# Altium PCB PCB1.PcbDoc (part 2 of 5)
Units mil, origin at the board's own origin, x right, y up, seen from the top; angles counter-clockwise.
Board outline 4463 x 4481 mil, 2 copper layers (Top Layer, Bottom Layer); 0 components, 111 nets, 310 pads, 0 vias.
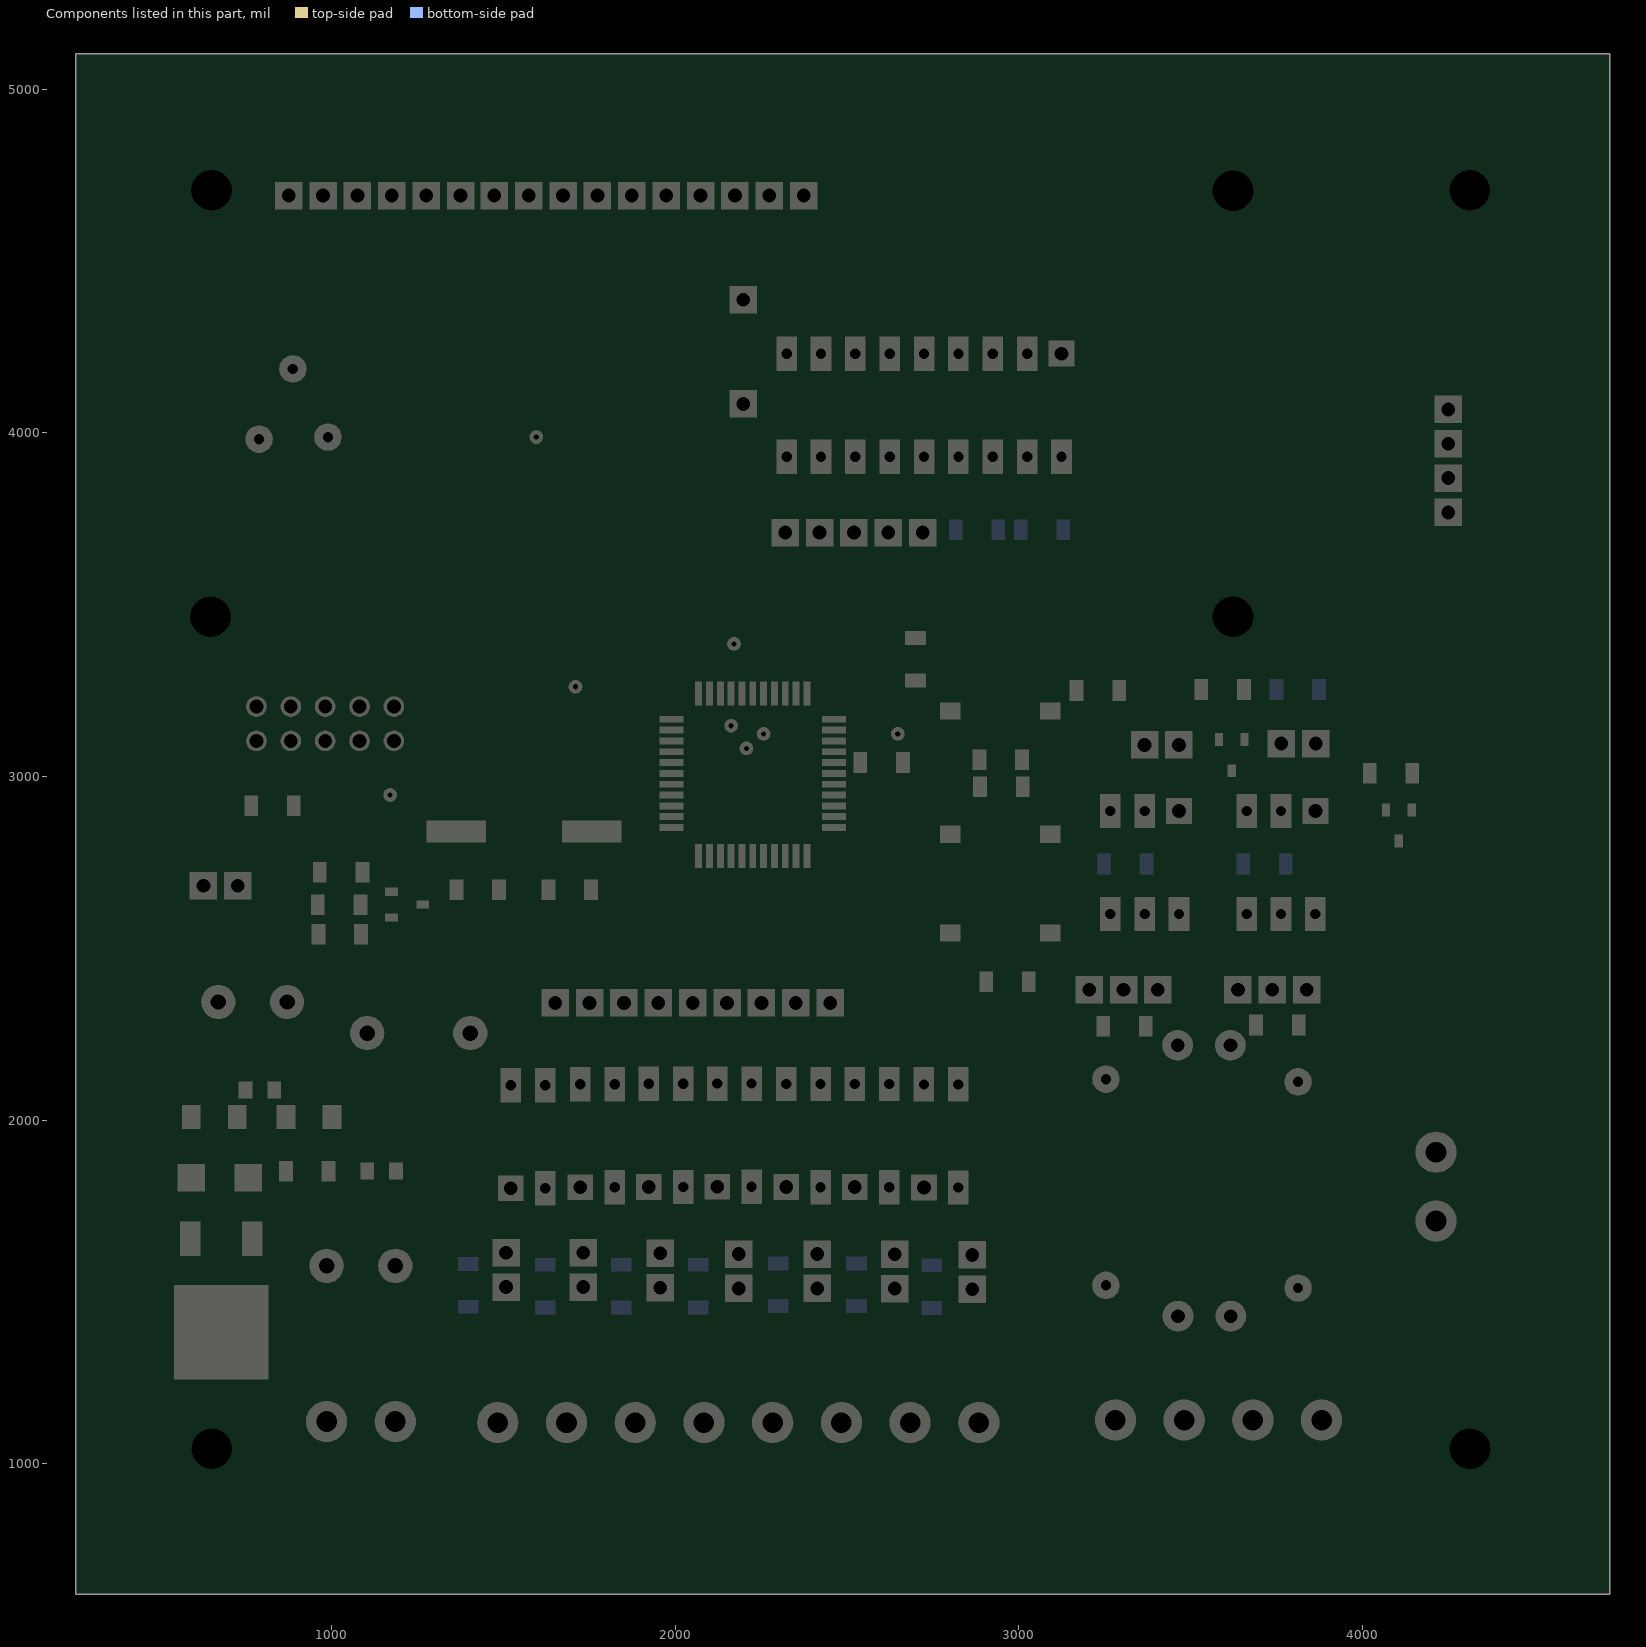
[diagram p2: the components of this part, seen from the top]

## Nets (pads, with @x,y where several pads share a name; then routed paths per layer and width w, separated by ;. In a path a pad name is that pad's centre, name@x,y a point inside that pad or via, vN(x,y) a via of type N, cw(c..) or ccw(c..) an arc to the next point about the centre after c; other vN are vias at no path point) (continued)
copper on no net: (continued)
  Top Layer w15: 514.04,931.9 4450.24,931.9 ; 514.04,956.9 4450.24,956.9 ; 514.04,981.9 591.54,981.9 ; 514.04,1006.9 566.54,1006.9 ; 514.04,1031.9 565.74,1031.9 ; 514.04,1056.9 565.74,1056.9 ; 514.04,1081.9 568.24,1081.9 ; 514.04,1106.9 593.24,1106.9 ; 514.04,1131.9 898.64,1131.9 ; 514.04,1156.9 898.64,1156.9 ; 514.04,1181.9 921.24,1181.9 ; 514.04,1206.9 946.24,1206.9 ; 514.04,1231.9 514.64,1231.9 ; 514.04,1256.9 514.64,1256.9 ; 514.04,1281.9 514.64,1281.9 ; 514.04,1306.9 514.64,1306.9 ; 514.04,1331.9 514.64,1331.9 ; 514.04,1356.9 514.64,1356.9 ; 514.04,1381.9 514.64,1381.9 ; 514.04,1406.9 514.64,1406.9 ; 514.04,1431.9 514.64,1431.9 ; 514.04,1456.9 514.64,1456.9 ; 514.04,1481.9 514.64,1481.9 ; 514.04,1506.9 514.64,1506.9 ; 514.04,1531.9 514.64,1531.9 ; 514.04,1556.9 908.64,1556.9 ; 514.04,1581.9 532.14,1581.9 ; 514.04,1606.9 532.14,1606.9 ; 514.04,1631.9 532.14,1631.9 ; 514.04,1656.9 532.14,1656.9 ; 514.04,1681.9 532.14,1681.9 ; 514.04,1706.9 532.14,1706.9 ; 514.04,1731.9 532.14,1731.9 ; 514.04,1756.9 547.14,1756.9 ; 514.04,1781.9 524.94,1781.9 ; 514.04,1806.9 524.94,1806.9 ; 514.04,1831.9 524.94,1831.9 ; 514.04,1856.9 524.94,1856.9 ; 514.04,1881.9 524.94,1881.9 ; 514.04,1906.9 549.94,1906.9 ; 514.04,1931.9 549.94,1931.9 ; 514.04,1956.9 537.44,1956.9 ; 514.04,1981.9 537.44,1981.9 ; 514.04,2006.9 537.44,2006.9 ; 514.04,2031.9 537.44,2031.9 ; 514.04,2056.9 537.44,2056.9 ; 514.04,2081.9 549.94,2081.9 ; 514.04,2106.9 571.34,2106.9 ; 514.04,2131.9 702.44,2131.9 ; 514.04,2156.9 709.94,2156.9 ; 514.04,2181.9 709.94,2181.9 ; 514.04,2206.9 709.94,2206.9 ; 514.04,2231.9 709.94,2231.9 ; 514.04,2256.9 709.94,2256.9 ; 514.04,2281.9 623.24,2281.9 ; 514.04,2306.9 598.24,2306.9 ; 514.04,2331.9 593.64,2331.9 ; 514.04,2356.9 593.64,2356.9 ; 514.04,2381.9 599.84,2381.9 ; 514.04,2406.9 624.84,2406.9 ; 514.04,2431.9 930.64,2431.9 ; 514.04,2456.9 930.64,2456.9 ; 514.04,2481.9 930.64,2481.9 ; 514.04,2506.9 911.04,2506.9 ; 514.04,2531.9 886.04,2531.9 ; 514.04,2556.9 872.34,2556.9 ; 514.04,2581.9 872.34,2581.9 ; 514.04,2606.9 872.34,2606.9 ; 514.04,2631.9 560.34,2631.9 ; 514.04,2656.9 560.34,2656.9 ; 514.04,2681.9 560.34,2681.9 ; 514.04,2706.9 560.34,2706.9 ; 514.04,2731.9 560.34,2731.9 ; 514.04,2756.9 692.84,2756.9 ; 514.04,2781.9 692.84,2781.9 ; 514.04,2806.9 692.84,2806.9 ; 514.04,2831.9 692.84,2831.9 ; 514.04,2856.9 707.84,2856.9 ; 514.04,2881.9 719.34,2881.9 ; 514.04,2906.9 719.34,2906.9 ; 514.04,2931.9 719.34,2931.9 ; 514.04,2956.9 719.34,2956.9 ; 514.04,2981.9 931.44,2981.9 ; 514.04,3006.9 674.04,3006.9 ; 514.04,3031.9 665.34,3031.9 ; 514.04,3056.9 665.34,3056.9 ; 514.04,3081.9 665.34,3081.9 ; 514.04,3106.9 665.34,3106.9 ; 514.04,3131.9 665.34,3131.9 ; 514.04,3156.9 665.34,3156.9 ; 514.04,3181.9 665.34,3181.9 ; 514.04,3206.9 665.34,3206.9 ; 514.04,3231.9 665.34,3231.9 ; 514.04,3256.9 675.34,3256.9 ; 514.04,3281.9 700.34,3281.9 ; 514.04,3306.9 725.34,3306.9 ; 514.04,3331.9 750.34,3331.9 ; 514.04,3356.9 754.64,3356.9 ; 514.04,3381.9 608.34,3381.9 ; 514.04,3406.9 583.34,3406.9 ; 514.04,3431.9 561.74,3431.9 ; 514.04,3456.9 561.74,3456.9 ; 514.04,3481.9 561.74,3481.9 ; 514.04,3506.9 568.44,3506.9 ; 514.04,3531.9 593.44,3531.9 ; 514.04,3556.9 754.64,3556.9 ; 514.04,3581.9 754.64,3581.9 ; 514.04,3606.9 754.64,3606.9 ; 514.04,3631.9 754.64,3631.9 ; 514.04,3656.9 754.64,3656.9 ; 514.04,3681.9 754.64,3681.9 ; 514.04,3706.9 754.64,3706.9 ; 514.04,3731.9 754.64,3731.9 ; 514.04,3756.9 754.64,3756.9 ; 514.04,3781.9 754.64,3781.9 ; 514.04,3806.9 754.64,3806.9 ; 514.04,3831.9 754.64,3831.9 ; 514.04,3856.9 754.64,3856.9 ; 514.04,3881.9 754.64,3881.9 ; 514.04,3906.9 754.64,3906.9 ; 514.04,3931.9 743.54,3931.9 ; 514.04,3956.9 722.14,3956.9 ; 514.04,3981.9 722.14,3981.9 ; 514.04,4006.9 722.14,4006.9 ; 514.04,4031.9 744.94,4031.9 ; 514.04,4056.9 1056.24,4056.9 ; 514.04,4081.9 1056.24,4081.9 ; 514.04,4106.9 1056.24,4106.9 ; 514.04,4131.9 846.34,4131.9 ; 514.04,4156.9 821.34,4156.9 ; 514.04,4181.9 820.64,4181.9 ; 514.04,4206.9 820.64,4206.9 ; 514.04,4231.9 839.04,4231.9 839.04,4433.2 ; 514.04,4256.9 1015.34,4256.9 ; 514.04,4281.9 990.34,4281.9 ; 514.04,4306.9 965.34,4306.9 ; 514.04,4331.9 940.34,4331.9 ; 514.04,4356.9 915.34,4356.9 ; 514.04,4381.9 890.34,4381.9 ; 514.04,4406.9 865.34,4406.9 ; 514.04,4431.9 840.34,4431.9 ; 514.04,4456.9 815.34,4456.9 ; 514.04,4481.9 790.34,4481.9 ; 514.04,4506.9 765.74,4506.9 ; 514.04,4531.9 765.74,4531.9 ; 514.04,4556.9 765.74,4556.9 ; 514.04,4581.9 765.74,4581.9 ; 514.04,4606.9 765.74,4606.9 ; 514.04,4631.9 602.84,4631.9 ; 514.04,4656.9 577.84,4656.9 ; 514.04,4681.9 564.94,4681.9 ; 514.04,4706.9 564.94,4706.9 ; 514.04,4731.9 564.94,4731.9 ; 514.04,4756.9 580.34,4756.9 ; 514.04,4781.9 605.34,4781.9 ; 514.04,4806.9 4450.24,4806.9 ; 514.04,4831.9 4450.24,4831.9 ; 539.04,906.9 539.04,1217.6 ; 539.04,1547.6 539.04,1577.1 ; 539.04,1732.1 539.04,1764.2 ; 539.04,1899.2 539.04,1946.4 ; 539.04,2071.4 539.04,4841.9 ; 564.04,906.9 564.04,1217.6 ; 564.04,1547.6 564.04,1577.1 ; 564.04,2099.7 564.04,2614.6 ; 564.04,2749.6 564.04,3426.2 ; 564.04,3502.5 564.04,4841.9 ; 589.04,906.9 589.04,984.4 ; 589.04,1102.7 589.04,1217.6 ; 589.04,1547.6 589.04,1577.1 ; 589.04,2124.7 589.04,2614.6 ; 589.04,2749.6 589.04,3401.2 ; 589.04,3527.5 589.04,4645.7 ; 589.04,4765.6 589.04,4841.9 ; 614.04,906.9 614.04,959.4 ; 614.04,1127.7 614.04,1217.6 ; 614.04,1547.6 614.04,1577.1 ; 614.04,2130.1 614.04,2291.1 ; 614.04,2396.1 614.04,2614.6 ; 614.04,2749.6 614.04,3377.8 ; 614.04,3550.9 614.04,4620.7 ; 614.04,4790.6 614.04,4841.9 ; 632.14,1756.9 715.24,1756.9 ; 634.94,1906.9 820.54,1906.9 ; 634.94,1931.9 825.54,1931.9 ; 639.04,906.9 639.04,957 ; 639.04,1130.1 639.04,1217.6 ; 639.04,1547.6 639.04,1577.1 ; 639.04,1732.1 639.04,1764.2 ; 639.04,1899.2 639.04,1946.4 ; 639.04,2130.1 639.04,2266.1 ; 639.04,2614.6 639.04,2421.1 ; 639.04,2749.6 639.04,3377.8 ; 639.04,3550.9 639.04,4619.1 ; 639.04,4792.2 639.04,4841.9 ; 647.14,1581.9 712.14,1581.9 ; 647.14,1606.9 712.14,1606.9 ; 647.14,1631.9 712.14,1631.9 ; 647.14,1656.9 712.14,1656.9 ; 647.14,1681.9 712.14,1681.9 ; 647.14,1706.9 712.14,1706.9 ; 647.14,1731.9 712.14,1731.9 ; 647.44,1956.9 671.24,1956.9 ; 647.44,1981.9 671.24,1981.9 ; 647.44,2006.9 671.24,2006.9 ; 647.44,2031.9 671.24,2031.9 ; 659.94,1781.9 690.94,1781.9 ; 659.94,1806.9 690.94,1806.9 ; 659.94,1831.9 690.94,1831.9 ; 659.94,1856.9 690.94,1856.9 ; 659.94,1881.9 690.94,1881.9 ; 664.04,906.9 664.04,957 ; 664.04,1130.1 664.04,1217.6 ; 664.04,1547.6 664.04,2045.1 ; 664.04,2130.1 664.04,2266.1 ; 664.04,2421.1 664.04,2614.6 ; 664.04,2749.6 664.04,3377.8 ; 664.04,3550.9 664.04,4619.1 ; 664.04,4792.2 664.04,4841.9 ; 688.24,3381.9 754.64,3381.9 ; 689.04,906.9 689.04,957.9 ; 689.04,1129.2 689.04,1217.6 ; 689.04,1547.6 689.04,1946.4 ; 689.04,2130.1 689.04,2266.1 ; 689.04,2421.1 689.04,2614.6 ; 689.04,2749.6 689.04,2991.9 ; 689.04,3270.6 689.04,3382.7 ; 689.04,3546 689.04,4620.8 ; 689.04,4790.5 689.04,4841.9 ; 697.64,4781.9 794.44,4781.9 ; 700.14,4631.9 765.74,4631.9 ; 703.14,3531.9 754.64,3531.9 ; 711.34,1106.9 898.64,1106.9 ; 713.04,981.9 4252.44,981.9 ; 713.24,3406.9 754.64,3406.9 ; 714.04,906.9 714.04,982.9 ; 714.04,1104.2 714.04,1217.6 ; 714.04,1547.6 714.04,1577.1 ; 714.04,1732.1 714.04,1764.2 ; 714.04,1899.2 714.04,1946.4 ; 714.04,2410.3 714.04,2614.6 ; 714.04,2863.1 714.04,2988.4 ; 714.04,3295.6 714.04,3407.7 ; 714.04,3521 714.04,4645.8 ; 714.04,4765.5 714.04,4841.9 ; 717.44,2406.9 824.84,2406.9 ; 722.64,4756.9 769.44,4756.9 ; 725.14,4656.9 765.74,4656.9 ; 728.14,3506.9 754.64,3506.9 ; 734.84,3431.9 754.64,3431.9 ; 734.84,3456.9 754.64,3456.9 ; 734.84,3481.9 754.64,3481.9 ; 736.34,1081.9 903.54,1081.9 ; 738.04,1006.9 4227.44,1006.9 ; 738.04,4681.9 765.74,4681.9 ; 738.04,4706.9 765.74,4706.9 ; 738.04,4731.9 765.74,4731.9 ; 738.84,1031.9 4226.64,1031.9 ; 738.84,1056.9 928.54,1056.9 ; 739.04,906.9 739.04,1217.6 ; 739.04,1547.6 739.04,1577.1 ; 739.04,1899.2 739.04,1946.4 ; 739.04,2385.3 739.04,2614.6 ; 739.04,2972.6 739.04,2988.4 ; 739.04,3320.6 739.04,3936.4 ; 739.04,4026 739.04,4841.9 ; 742.44,2381.9 799.84,2381.9 ; 762.84,2756.9 918.94,2756.9 ; 762.84,2781.9 931.44,2781.9 ; 762.84,2806.9 931.44,2806.9 ; 764.04,906.9 764.04,1217.6 ; 764.04,1547.6 764.04,1577.1 ; 764.04,1899.2 764.04,1946.4 ; 764.04,2359.3 764.04,2614.6 ; 764.04,2749.6 764.04,2814.1 ; 764.04,2972.6 764.04,2988.4 ; 764.04,4048.7 764.04,4841.9 ; 766.44,2356.9 793.64,2356.9 ; 781.24,1956.9 813.04,1956.9 ; 781.84,2831.9 931.44,2831.9 ; 789.04,906.9 789.04,1217.6 ; 789.04,1547.6 789.04,1577.1 ; 789.04,1899.2 789.04,1966.4 ; 789.04,2334.3 789.04,2614.6 ; 789.04,2749.6 789.04,2839.1 ; 789.04,2972.6 789.04,2988.4 ; 789.04,4048.7 789.04,4483.2 ; 789.04,4776.5 789.04,4841.9 ; 789.94,2156.9 793.94,2156.9 ; 789.94,2181.9 793.94,2181.9 ; 789.94,2206.9 793.94,2206.9 ; 789.94,2231.9 805.04,2231.9 ; 789.94,2256.9 830.04,2256.9 ; 789.94,2281.9 823.24,2281.9 ; 789.94,2306.9 798.24,2306.9 ; 789.94,2331.9 793.64,2331.9 ; 795.34,2631.9 872.34,2631.9 ; 795.34,2656.9 872.34,2656.9 ; 795.34,2681.9 872.34,2681.9 ; 795.34,2706.9 872.34,2706.9 ; 795.34,2731.9 891.94,2731.9 ; 801.84,2856.9 931.44,2856.9 ; 814.04,906.9 814.04,1217.6 ; 814.04,1547.6 814.04,1577.1 ; 814.04,1899.2 814.04,1946.4 ; 814.04,2240.9 814.04,2291.1 ; 814.04,2396.1 814.04,2857.7 ; 814.04,2972.6 814.04,2988.4 ; 814.04,4048.7 814.04,4458.2 ; 814.04,4798.1 814.04,4841.9 ; 814.34,2881.9 843.34,2881.9 ; 814.34,2906.9 843.34,2906.9 ; 814.34,2931.9 843.34,2931.9 ; 814.34,2956.9 843.34,2956.9 ; 824.64,3356.9 841.84,3356.9 ; 824.64,3381.9 866.84,3381.9 ; 824.64,3406.9 891.84,3406.9 ; 824.64,3431.9 916.84,3431.9 ; 824.64,3456.9 941.84,3456.9 ; 824.64,3481.9 966.84,3481.9 ; 824.64,3506.9 991.84,3506.9 ; 824.64,3531.9 1016.84,3531.9 ; 824.64,3556.9 1041.84,3556.9 ; 824.64,3581.9 1056.24,3581.9 ; 824.64,3606.9 1056.24,3606.9 ; 824.64,3631.9 1056.24,3631.9 ; 824.64,3656.9 1056.24,3656.9 ; 824.64,3681.9 1056.24,3681.9 ; 824.64,3706.9 1056.24,3706.9 ; 824.64,3731.9 1056.24,3731.9 ; 824.64,3756.9 1056.24,3756.9 ; 824.64,3781.9 1056.24,3781.9 ; 824.64,3806.9 1056.24,3806.9 ; 824.64,3831.9 1056.24,3831.9 ; 824.64,3856.9 1056.24,3856.9 ; 824.64,3881.9 1056.24,3881.9 ; 824.64,3906.9 1056.24,3906.9 ; 827.14,1581.9 908.64,1581.9 ; 827.14,1606.9 908.64,1606.9 ; 834.44,4031.9 939.34,4031.9 ; 835.74,3931.9 949.94,3931.9 ; 839.04,906.9 839.04,1217.6 ; 839.04,1547.6 839.04,1614.6 ; 839.04,2265.9 839.04,2266.1 ; 839.04,2988.4 839.04,2421.1 ; 839.04,3354.1 839.04,3935.2 ; 839.04,4027.3 839.04,4139.2 ; 839.04,4798.1 839.04,4841.9 ; 844.64,1231.9 1312.04,1231.9 ; 844.64,1256.9 1287.04,1256.9 ; 844.64,1281.9 1277.44,1281.9 ; 844.64,1306.9 1277.44,1306.9 ; 844.64,1331.9 1277.44,1331.9 ; 844.64,1431.9 1059.84,1431.9 ; 844.64,1456.9 1084.84,1456.9 ; 844.64,1481.9 1109.84,1481.9 ; 844.64,1506.9 945.44,1506.9 ; 844.64,1531.9 920.44,1531.9 ; 857.14,3956.9 924.94,3956.9 ; 857.14,3981.9 922.54,3981.9 ; 857.14,4006.9 922.54,4006.9 ; 864.04,906.9 864.04,1335.1 ; 864.04,1430.1 864.04,1614.6 ; 864.04,2421.1 864.04,2857.7 ; 864.04,2972.6 864.04,2988.4 ; 864.04,3379.1 864.04,4118.1 ; 864.04,4253.1 864.04,4408.2 ; 864.04,4798.1 864.04,4841.9 ; 889.04,906.9 889.04,1335.1 ; 889.04,1430.1 889.04,1614.6 ; 889.04,2421.1 889.04,2528.9 ; 889.04,2729.1 889.04,2857.7 ; 889.04,2972.6 889.04,2988.4 ; 889.04,3404.1 889.04,4118.1 ; 889.04,4253.1 889.04,4383.2 ; 889.04,4798.1 889.04,4841.9 ; 914.04,906.9 914.04,1071.4 ; 914.04,1174.8 914.04,1335.1 ; 914.04,1430.1 914.04,1538.3 ; 914.04,1613.4 914.04,1614.6 ; 914.04,2410.3 914.04,2505.4 ; 914.04,2754.1 914.04,2857.7 ; 914.04,2972.6 914.04,2988.4 ; 914.04,3429.1 914.04,4118.1 ; 914.04,4253.1 914.04,4358.2 ; 914.04,4798.1 914.04,4841.9 ; 917.44,2406.9 930.64,2406.9 ; 929.94,4131.9 1056.24,4131.9 ; 937.24,4231.9 1040.34,4231.9 ; 939.04,906.9 939.04,1046.4 ; 939.04,1199.8 939.04,1335.1 ; 939.04,1430.1 939.04,1513.3 ; 939.04,3454.1 939.04,3942.7 ; 939.04,4031.6 939.04,4141 ; 939.04,4230.1 939.04,4333.2 ; 939.04,4798.1 939.04,4841.9 ; 954.94,4156.9 1056.24,4156.9 ; 955.64,4181.9 1056.24,4181.9 ; 955.64,4206.9 1056.24,4206.9 ; 964.04,906.9 964.04,1035.6 ; 964.04,1210.6 964.04,1335.1 ; 964.04,1430.1 964.04,1498.3 ; 964.04,3479.1 964.04,3919.7 ; 964.04,4054.7 964.04,4308.2 ; 964.04,4798.1 964.04,4841.9 ; 989.04,906.9 989.04,1035.6 ; 989.04,1210.6 989.04,1335.1 ; 989.04,1430.1 989.04,1498.3 ; 989.04,3504.1 989.04,3919.7 ; 989.04,4054.7 989.04,4283.2 ; 989.04,4798.1 989.04,4841.9 ; 1014.04,906.9 1014.04,1035.6 ; 1014.04,1210.6 1014.04,1335.1 ; 1014.04,1430.1 1014.04,1498.3 ; 1014.04,3529.1 1014.04,3919.7 ; 1014.04,4054.7 1014.04,4258.2 ; 1014.04,4798.1 1014.04,4841.9 ; 1026.04,1206.9 1146.24,1206.9 ; 1026.14,1656.9 1148.24,1656.9 ; 1026.14,1681.9 1148.24,1681.9 ; 1026.14,1706.9 1148.24,1706.9 ; 1026.84,1506.9 1134.84,1506.9 ; 1030.24,3931.9 1056.24,3931.9 ; 1032.04,1731.9 1148.24,1731.9 ; 1032.04,1756.9 1148.24,1756.9 ; 1032.04,1781.9 1148.24,1781.9 ; 1039.04,906.9 1039.04,1052.3 ; 1039.04,1193.9 1039.04,1335.1 ; 1039.04,1430.1 1039.04,1519.1 ; 1039.04,1632.5 1039.04,1793.9 ; 1039.04,3554.1 1039.04,3940.7 ; 1039.04,4033.6 1039.04,4233.2 ; 1039.04,4798.1 1039.04,4841.9 ; 1039.54,1806.9 1056.74,1806.9 ; 1039.64,1631.9 1132.64,1631.9 ; 1040.84,4031.9 1056.24,4031.9 ; 1043.74,1056.9 1128.54,1056.9 ; 1051.04,1181.9 1121.24,1181.9 ; 1051.84,1531.9 1120.44,1531.9 ; 1055.24,3956.9 1056.24,3956.9 ; 1063.64,1556.9 1108.64,1556.9 ; 1063.64,1581.9 1108.64,1581.9 ; 1063.64,1606.9 1108.64,1606.9 ; 1064.04,906.9 1064.04,1077.3 ; 1064.04,1168.9 1064.04,1335.1 ; 1064.04,1436.2 1064.04,1798.9 ; 1064.04,4798.1 1064.04,4841.9 ; 1068.74,1081.9 1103.54,1081.9 ; 1073.64,1106.9 1098.64,1106.9 ; 1073.64,1131.9 1098.64,1131.9 ; 1073.64,1156.9 1098.64,1156.9 ; 1089.04,906.9 1089.04,1335.1 ; 1089.04,1461.2 1089.04,1798.9 ; 1089.04,4798.1 1089.04,4841.9 ; 1114.04,906.9 1114.04,1071.4 ; 1114.04,1174.8 1114.04,1351.8 ; 1114.04,1486.2 1114.04,1538.3 ; 1114.04,1613.3 1114.04,1798.9 ; 1114.04,4798.1 1114.04,4841.9 ; 1119.14,1356.9 1277.44,1356.9 ; 1139.04,906.9 1139.04,1046.4 ; 1139.04,1199.8 1139.04,1376.8 ; 1139.04,1638.3 1139.04,1798.9 ; 1139.04,4798.1 1139.04,4841.9 ; 1144.14,1381.9 1277.44,1381.9 ; 1164.04,906.9 1164.04,1035.6 ; 1164.04,1210.6 1164.04,1401.8 ; 1164.04,4798.1 1164.04,4841.9 ; 1169.14,1406.9 1277.44,1406.9 ; 1189.04,906.9 1189.04,1035.6 ; 1189.04,1210.6 1189.04,1426.8 ; 1189.04,4798.1 1189.04,4841.9 ; 1194.14,1431.9 1277.44,1431.9 ; 1214.04,906.9 1214.04,1035.6 ; 1214.04,1210.6 1214.04,1451.8 ; 1214.04,4798.1 1214.04,4841.9 ; 1219.14,1456.9 1277.44,1456.9 ; 1226.04,1206.9 1337.04,1206.9 ; 1228.24,1656.9 1277.44,1656.9 ; 1228.24,1681.9 1277.44,1681.9 ; 1228.24,1706.9 1277.44,1706.9 ; 1228.24,1731.9 1277.44,1731.9 ; 1228.24,1756.9 1277.44,1756.9 ; 1228.24,1781.9 1277.44,1781.9 ; 1233.64,1481.9 1277.44,1481.9 ; 1233.64,1506.9 1277.44,1506.9 ; 1235.74,1806.9 1277.44,1806.9 ; 1239.04,906.9 1239.04,1052.3 ; 1239.04,1193.9 1239.04,1519.1 ; 1239.04,1632.5 1239.04,1811.4 ; 1239.04,4798.1 1239.04,4841.9 ; 1239.64,1631.9 1277.44,1631.9 ; 1243.74,1056.9 1423.44,1056.9 ; 1251.04,1181.9 1362.04,1181.9 ; 1251.84,1531.9 1277.44,1531.9 ; 1263.64,1556.9 1277.44,1556.9 ; 1263.64,1581.9 1277.44,1581.9 ; 1263.64,1606.9 1277.44,1606.9 ; 1264.04,906.9 1264.04,1077.3 ; 1264.04,1168.9 1264.04,1811.8 ; 1264.04,4798.1 1264.04,4841.9 ; 1268.74,1081.9 1398.44,1081.9 ; 1273.64,1106.9 1396.64,1106.9 ; 1273.64,1131.9 1396.64,1131.9 ; 1273.64,1156.9 1387.04,1156.9 ; 1287.14,2256.9 1296.04,2256.9 ; 1287.14,2281.9 1321.04,2281.9 ; 1287.14,2306.9 1348.54,2306.9 ; 1287.14,2331.9 1583.94,2331.9 ; 1289.04,906.9 1289.04,1254.9 ; 1289.04,2249.9 1289.04,2346.2 ; 1289.04,4798.1 1289.04,4841.9 ; 1299.74,2356.9 1583.94,2356.9 ; 1314.04,906.9 1314.04,1229.9 ; 1314.04,2274.9 1314.04,2371.2 ; 1314.04,4798.1 1314.04,4841.9 ; 1324.74,2381.9 1583.94,2381.9 ; 1339.04,906.9 1339.04,1204.9 ; 1339.04,2297.4 1339.04,2396.2 ; 1339.04,4798.1 1339.04,4841.9 ; 1349.74,2406.9 1583.94,2406.9 ; 1356.84,2431.9 1714.14,2431.9 ; 1356.84,2456.9 1714.14,2456.9 ; 1356.84,2481.9 1714.14,2481.9 ; 1356.84,2506.9 1714.14,2506.9 ; 1356.84,2531.9 1714.14,2531.9 ; 1362.44,1306.9 4450.24,1306.9 ; 1362.44,1331.9 4450.24,1331.9 ; 1362.44,1356.9 4450.24,1356.9 ; 1362.44,1381.9 3408.64,1381.9 ; 1362.44,1406.9 3391.14,1406.9 ; 1362.44,1431.9 3391.14,1431.9 ; 1362.44,1456.9 1441.04,1456.9 ; 1362.44,1481.9 1441.04,1481.9 ; 1362.44,1506.9 1441.04,1506.9 ; 1362.44,1531.9 1441.04,1531.9 ; 1362.44,1556.9 1441.04,1556.9 ; 1362.44,1581.9 1441.04,1581.9 ; 1362.44,1606.9 1441.04,1606.9 ; 1362.44,1631.9 1441.04,1631.9 ; 1362.44,1656.9 1441.04,1656.9 ; 1362.44,1681.9 4126.84,1681.9 ; 1362.44,1706.9 4126.84,1706.9 ; 1362.44,1731.9 1564.84,1731.9 ; 1362.44,1756.9 1457.34,1756.9 ; 1362.44,1781.9 1457.34,1781.9 ; 1362.44,1806.9 1457.34,1806.9 ; 1362.44,1831.9 1457.34,1831.9 ; 1362.44,1856.9 1457.34,1856.9 ; 1362.44,1881.9 1766.84,1881.9 ; 1362.44,1906.9 4126.84,1906.9 ; 1362.44,1931.9 4126.84,1931.9 ; 1362.44,1956.9 4140.94,1956.9 ; 1362.44,1981.9 4165.94,1981.9 ; 1362.44,2006.9 4450.24,2006.9 ; 1362.44,2031.9 1464.84,2031.9 ; 1362.44,2056.9 1464.84,2056.9 ; 1362.44,2081.9 1464.84,2081.9 ; 1362.44,2106.9 1464.84,2106.9 ; 1362.44,2131.9 1464.84,2131.9 ; 1362.44,2156.9 1464.84,2156.9 ; 1362.44,2181.9 1365.74,2181.9 ; 1364.04,906.9 1364.04,1179.9 ; 1364.04,1300.1 1364.04,2183.6 ; 1364.04,2322.4 1364.04,2540.8 ; 1364.04,2610.8 1364.04,2612.8 ; 1364.04,4798.1 1364.04,4841.9 ; 1382.24,1281.9 4450.24,1281.9 ; 1389.04,906.9 1389.04,1154.9 ; 1389.04,1275.1 1389.04,2175.5 ; 1389.04,2330.5 1389.04,2540.8 ; 1389.04,2610.8 1389.04,2612.8 ; 1389.04,4786.4 1389.04,4841.9 ; 1393.64,4781.9 3578.84,4781.9 ; 1399.04,2731.9 1720.84,2731.9 ; 1399.04,2756.9 1720.84,2756.9 ; 1407.24,1256.9 4450.24,1256.9 ; 1411.54,2631.9 1440.54,2631.9 ; 1411.54,2656.9 1440.54,2656.9 ; 1411.54,2681.9 1440.54,2681.9 ; 1411.54,2706.9 1440.54,2706.9 ; 1414.04,906.9 1414.04,1066.3 ; 1414.04,1250.1 1414.04,2175.5 ; 1414.04,2330.5 1414.04,2540.8 ; 1414.04,2610.8 1414.04,2780.6 ; 1414.04,4757.4 1414.04,4841.9 ; 1432.24,1231.9 4450.24,1231.9 ; 1439.04,906.9 1439.04,1041.3 ; 1439.04,1225.1 1439.04,2178.2 ; 1439.04,2327.8 1439.04,2540.8 ; 1439.04,2610.8 1439.04,2780.6 ; 1439.04,4757.4 1439.04,4841.9 ; 1442.74,2181.9 1666.84,2181.9 ; 1459.94,2306.9 1583.94,2306.9 ; 1464.04,906.9 1464.04,1032.4 ; 1464.04,1207.4 1464.04,1446.5 ; 1464.04,1681.5 1464.04,1736.4 ; 1464.04,1866.4 1464.04,2203.2 ; 1464.04,2302.8 1464.04,2540.8 ; 1464.04,2727.8 1464.04,2780.6 ; 1464.04,4757.4 1464.04,4841.9 ; 1467.74,2206.9 2994.34,2206.9 ; 1478.04,2781.9 1643.74,2781.9 ; 1481.74,2231.9 2994.34,2231.9 ; 1481.74,2256.9 2994.34,2256.9 ; 1481.74,2281.9 1583.94,2281.9 ; 1489.04,906.9 1489.04,1032.4 ; 1489.04,1207.4 1489.04,1446.5 ; 1489.04,1681.5 1489.04,1736.4 ; 1489.04,1866.4 1489.04,2023.9 ; 1489.04,2178.9 1489.04,2540.8 ; 1489.04,2727.8 1489.04,2804.6 ; 1489.04,4757.4 1489.04,4841.9 ; 1514.04,906.9 1514.04,1032.4 ; 1514.04,1207.4 1514.04,1446.5 ; 1514.04,1681.5 1514.04,1736.4 ; 1514.04,1866.4 1514.04,2023.9 ; 1514.04,2178.9 1514.04,2552.3 ; 1514.04,2727.8 1514.04,2804.6 ; 1514.04,4757.4 1514.04,4841.9 ; 1518.64,2556.9 1714.14,2556.9 ; 1520.94,1206.9 1647.44,1206.9 ; 1523.04,2581.9 1717.94,2581.9 ; 1523.04,2606.9 1742.94,2606.9 ; 1535.54,2631.9 1584.34,2631.9 ; 1535.54,2706.9 1584.34,2706.9 ; 1539.04,906.9 1539.04,1051.1 ; 1539.04,1188.8 1539.04,1446.5 ; 1539.04,1681.5 1539.04,1736.4 ; 1539.04,1866.4 1539.04,2023.9 ; 1539.04,2178.9 1539.04,2635.3 ; 1539.04,2705.3 1539.04,2804.6 ; 1539.04,4757.4 1539.04,4841.9 ; 1542.34,2806.9 1643.74,2806.9 ; 1544.94,1056.9 1623.44,1056.9 ; 1545.94,1181.9 1622.44,1181.9 ; 1564.04,906.9 1564.04,1076.1 ; 1564.04,1163.8 1564.04,1446.5 ; 1564.04,1681.5 1564.04,1736.4 ; 1564.04,1866.4 1564.04,2023.9 ; 1564.04,2178.9 1564.04,2635.3 ; 1564.04,2705.3 1564.04,2828.6 ; 1564.04,4757.4 1564.04,4841.9 ; 1567.34,2831.9 1643.74,2831.9 ; 1569.94,1081.9 1598.44,1081.9 ; 1570.94,1156.9 1597.44,1156.9 ; 1571.64,1106.9 1596.64,1106.9 ; 1571.64,1131.9 1596.64,1131.9 ; 1576.04,1456.9 1665.44,1456.9 ; 1576.04,1481.9 1665.44,1481.9 ; 1576.04,1506.9 1665.44,1506.9 ; 1576.04,1531.9 1665.44,1531.9 ; 1576.04,1556.9 1665.44,1556.9 ; 1576.04,1581.9 1665.44,1581.9 ; 1576.04,1606.9 1665.44,1606.9 ; 1576.04,1631.9 1665.44,1631.9 ; 1576.04,1656.9 1665.44,1656.9 ; 1589.04,906.9 1589.04,1723.9 ; 1589.04,1878.9 1589.04,2023.9 ; 1589.04,2178.9 1589.04,2273.3 ; 1589.04,2408.3 1589.04,2612.8 ; 1589.04,2727.8 1589.04,2853.6 ; 1589.04,4757.4 1589.04,4841.9 ; 1592.34,2856.9 1643.74,2856.9 ; 1614.04,906.9 1614.04,1066.3 ; 1614.04,1173.6 1614.04,1723.9 ; 1614.04,1878.9 1614.04,2023.9 ; 1614.04,2178.9 1614.04,2273.3 ; 1614.04,2408.3 1614.04,2612.8 ; 1614.04,2727.8 1614.04,2878.6 ; 1614.04,4757.4 1614.04,4841.9 ; 1617.34,2881.9 1643.74,2881.9 ; 1639.04,906.9 1639.04,1041.3 ; 1639.04,1198.6 1639.04,1723.9 ; 1639.04,1878.9 1639.04,2023.9 ; 1639.04,2178.9 1639.04,2273.3 ; 1639.04,2408.3 1639.04,2612.8 ; 1639.04,2727.8 1639.04,2903.6 ; 1639.04,4757.4 1639.04,4841.9 ; 1642.34,2906.9 1724.54,2906.9 ; 1664.04,906.9 1664.04,1032.4 ; 1664.04,1207.4 1664.04,1723.9 ; 1664.04,1878.9 1664.04,2023.9 ; 1664.04,2178.9 1664.04,2273.3 ; 1664.04,2408.3 1664.04,2612.8 ; 1664.04,2727.8 1664.04,2780.6 ; 1664.04,2898.5 1664.04,2928.6 ; 1664.04,4757.4 1664.04,4841.9 ; 1667.34,2931.9 1749.54,2931.9 ; 1679.34,2631.9 1708.34,2631.9 ; 1679.34,2656.9 1708.34,2656.9 ; 1679.34,2681.9 1708.34,2681.9 ; 1679.34,2706.9 1708.34,2706.9 ; 1679.84,1731.9 1766.84,1731.9 ; 1689.04,906.9 1689.04,1032.4 ; 1689.04,1207.4 1689.04,1446.5 ; 1689.04,1681.5 1689.04,1739.6 ; 1689.04,1869.6 1689.04,2027.1 ; 1689.04,2182.1 1689.04,2273.3 ; 1689.04,2408.3 1689.04,2780.6 ; 1689.04,2898.5 1689.04,2942.3 ; 1689.04,4757.4 1689.04,4841.9 ; 1714.04,906.9 1714.04,1032.4 ; 1714.04,1207.4 1714.04,1446.5 ; 1714.04,1681.5 1714.04,1739.6 ; 1714.04,1869.6 1714.04,2027.1 ; 1714.04,2182.1 1714.04,2273.3 ; 1714.04,2408.3 1714.04,2612.8 ; 1714.04,2727.8 1714.04,2780.6 ; 1714.04,2898.5 1714.04,2942.3 ; 1714.04,4757.4 1714.04,4841.9 ; 1720.94,1206.9 1847.44,1206.9 ; 1739.04,906.9 1739.04,1051.1 ; 1739.04,1188.8 1739.04,1446.5 ; 1739.04,1681.5 1739.04,1739.6 ; 1739.04,1869.6 1739.04,2027.1 ; 1739.04,2182.1 1739.04,2273.3 ; 1739.04,2603 1739.04,2612.8 ; 1739.04,2921.4 1739.04,2942.3 ; 1739.04,4757.4 1739.04,4841.9 ; 1744.94,1056.9 1823.44,1056.9 ; 1745.94,1181.9 1822.44,1181.9 ; 1764.04,906.9 1764.04,1076.1 ; 1764.04,1163.8 1764.04,1446.5 ; 1764.04,1681.5 1764.04,1739.6 ; 1764.04,1869.6 1764.04,2027.1 ; 1764.04,2182.1 1764.04,2273.3 ; 1764.04,4757.4 1764.04,4841.9 ; 1769.94,1081.9 1798.44,1081.9 ; 1770.94,1156.9 1797.44,1156.9 ; 1771.64,1106.9 1796.64,1106.9 ; 1771.64,1131.9 1796.64,1131.9 ; 1789.04,906.9 1789.04,1446.5 ; 1789.04,1681.5 1789.04,1727.1 ; 1789.04,1882.1 1789.04,2027.1 ; 1789.04,2182.1 1789.04,2273.3 ; 1789.04,4757.4 1789.04,4841.9 ; 1800.44,1456.9 1889.84,1456.9 ; 1800.44,1481.9 1889.84,1481.9 ; 1800.44,1506.9 1889.84,1506.9 ; 1800.44,1531.9 1889.84,1531.9 ; 1800.44,1556.9 1889.84,1556.9 ; 1800.44,1581.9 1889.84,1581.9 ; 1800.44,1606.9 1889.84,1606.9 ; 1800.44,1631.9 1889.84,1631.9 ; 1800.44,1656.9 1889.84,1656.9 ; 1814.04,906.9 1814.04,1066.3 ; 1814.04,1173.6 1814.04,1727.1 ; 1814.04,1882.1 1814.04,2027.1 ; 1814.04,2182.1 1814.04,2273.3 ; 1814.04,4757.4 1814.04,4841.9 ; 1839.04,906.9 1839.04,1041.3 ; 1839.04,1198.6 1839.04,1727.1 ; 1839.04,1882.1 1839.04,2027.1 ; 1839.04,2182.1 1839.04,2273.3 ; 1839.04,4757.4 1839.04,4841.9 ; 1864.04,906.9 1864.04,1032.4 ; 1864.04,1207.4 1864.04,1727.1 ; 1864.04,1882.1 1864.04,2027.1 ; 1864.04,2182.1 1864.04,2273.3 ; 1864.04,4757.4 1864.04,4841.9 ; 1881.84,1731.9 1966.04,1731.9 ; 1881.84,1881.9 1966.04,1881.9 ; 1889.04,906.9 1889.04,1032.4 ; 1889.04,1207.4 1889.04,1740.4 ; 1889.04,1870.4 1889.04,2027.9 ; 1889.04,2182.9 1889.04,2273.3 ; 1889.04,4757.4 1889.04,4841.9 ; 1914.04,906.9 1914.04,1032.4 ; 1914.04,1207.4 1914.04,1445 ; 1914.04,1680 1914.04,1740.4 ; 1914.04,1870.4 1914.04,2027.9 ; 1914.04,2182.9 1914.04,2273.3 ; 1914.04,4757.4 1914.04,4841.9 ; 1920.94,1206.9 2047.44,1206.9 ; 1939.04,906.9 1939.04,1051.1 ; 1939.04,1188.8 1939.04,1445 ; 1939.04,1680 1939.04,1740.4 ; 1939.04,1870.4 1939.04,2027.9 ; 1939.04,2182.9 1939.04,2273.3 ; 1939.04,4757.4 1939.04,4841.9 ; 1944.94,1056.9 2023.44,1056.9 ; 1945.94,1181.9 2022.44,1181.9 ; 1964.04,906.9 1964.04,1076.1 ; 1964.04,1163.8 1964.04,1445 ; 1964.04,1680 1964.04,1740.4 ; 1964.04,1870.4 1964.04,2027.9 ; 1964.04,2182.9 1964.04,2273.3 ; 1964.04,4757.4 1964.04,4841.9 ; 1969.94,1081.9 1998.44,1081.9 ; 1970.94,1156.9 1997.44,1156.9 ; 1971.64,1106.9 1996.64,1106.9 ; 1971.64,1131.9 1996.64,1131.9 ; 1989.04,906.9 1989.04,1445 ; 1989.04,1680 1989.04,1727.9 ; 1989.04,1882.9 1989.04,2027.9 ; 1989.04,2182.9 1989.04,2273.3 ; 1989.04,4757.4 1989.04,4841.9 ; 2014.04,906.9 2014.04,1066.3 ; 2014.04,1173.6 2014.04,1445 ; 2014.04,1680 2014.04,1727.9 ; 2014.04,1882.9 2014.04,2027.9 ; 2014.04,2182.9 2014.04,2273.3 ; 2014.04,4757.4 2014.04,4841.9 ; 2024.84,1456.9 2118.24,1456.9 ; 2024.84,1481.9 2118.24,1481.9 ; 2024.84,1506.9 2118.24,1506.9 ; 2024.84,1531.9 2118.24,1531.9 ; 2024.84,1556.9 2118.24,1556.9 ; 2024.84,1581.9 2118.24,1581.9 ; 2024.84,1606.9 2118.24,1606.9 ; 2024.84,1631.9 2118.24,1631.9 ; 2024.84,1656.9 2118.24,1656.9 ; 2039.04,906.9 2039.04,1041.3 ; 2039.04,1198.6 2039.04,1727.9 ; 2039.04,1882.9 2039.04,2027.9 ; 2039.04,2182.9 2039.04,2273.3 ; 2039.04,4757.4 2039.04,4841.9 ; 2064.04,906.9 2064.04,1032.4 ; 2064.04,1207.4 2064.04,1727.9 ; 2064.04,1882.9 2064.04,2027.9 ; 2064.04,2182.9 2064.04,2273.3 ; 2064.04,4757.4 2064.04,4841.9 ; 2081.04,1731.9 2165.24,1731.9 ; 2081.04,1881.9 2165.24,1881.9 ; 2089.04,906.9 2089.04,1032.4 ; 2089.04,1207.4 2089.04,1741.2 ; 2089.04,1871.2 2089.04,2028.7 ; 2089.04,2183.7 2089.04,2273.3 ; 2089.04,4757.4 2089.04,4841.9 ; 2114.04,906.9 2114.04,1032.4 ; 2114.04,1207.4 2114.04,1741.2 ; 2114.04,1871.2 2114.04,2028.7 ; 2114.04,2183.7 2114.04,2273.3 ; 2114.04,4757.4 2114.04,4841.9 ; 2120.94,1206.9 2247.44,1206.9 ; 2127.44,3431.9 2150.74,3431.9 ; 2127.44,3456.9 2222.74,3456.9 ; 2127.44,3481.9 2222.74,3481.9 ; 2127.44,3506.9 2222.74,3506.9 ; 2127.44,3531.9 2222.74,3531.9 ; 2127.44,3556.9 2222.74,3556.9 ; 2127.44,3581.9 2213.94,3581.9 ; 2127.44,3606.9 2188.94,3606.9 ; 2127.44,3631.9 2163.94,3631.9 ; 2127.44,3656.9 2163.74,3656.9 ; 2127.44,3681.9 2163.74,3681.9 ; 2127.44,3706.9 2163.74,3706.9 ; 2127.44,3731.9 2163.74,3731.9 ; 2127.44,3756.9 2163.74,3756.9 ; 2127.44,3781.9 2163.74,3781.9 ; 2127.44,3806.9 2163.74,3806.9 ; 2127.44,3831.9 2163.74,3831.9 ; 2127.44,3856.9 2163.74,3856.9 ; 2127.44,3881.9 2163.74,3881.9 ; 2127.44,3906.9 2163.74,3906.9 ; 2127.44,3931.9 2163.74,3931.9 ; 2127.44,3956.9 2163.74,3956.9 ; 2127.44,3981.9 2163.74,3981.9 ; 2127.44,4006.9 2163.74,4006.9 ; 2127.44,4031.9 2131.24,4031.9 ; 2127.44,4056.9 2131.24,4056.9 ; 2127.44,4081.9 2131.24,4081.9 ; 2127.44,4106.9 2131.24,4106.9 ; 2127.44,4131.9 2131.24,4131.9 ; 2127.44,4156.9 2267.24,4156.9 ; 2127.44,4181.9 2267.24,4181.9 ; 2127.44,4206.9 2267.24,4206.9 ; 2127.44,4231.9 2267.24,4231.9 ; 2127.44,4256.9 2267.24,4256.9 ; 2127.44,4281.9 2267.24,4281.9 ; 2127.44,4306.9 2267.24,4306.9 ; 2127.44,4331.9 2131.24,4331.9 ; 2127.44,4356.9 2131.24,4356.9 ; 2127.44,4381.9 2131.24,4381.9 ; 2127.44,4406.9 2131.24,4406.9 ; 2127.44,4431.9 2131.24,4431.9 ; 2127.44,4456.9 4450.24,4456.9 ; 2127.44,4481.9 4450.24,4481.9 ; 2139.04,906.9 2139.04,1051.1 ; 2139.04,1188.8 2139.04,1442.6 ; 2139.04,1677.6 2139.04,1741.2 ; 2139.04,1871.2 2139.04,2028.7 ; 2139.04,2183.7 2139.04,2273.3 ; 2139.04,3420.2 2139.04,4016.1 ; 2139.04,4151.1 2139.04,4319.3 ; 2139.04,4454.3 2139.04,4498 ; 2139.04,4757.4 2139.04,4841.9 ; 2144.94,1056.9 2223.44,1056.9 ; 2145.94,1181.9 2222.44,1181.9 ; 2147.94,4506.9 4450.24,4506.9 ; 2164.04,906.9 2164.04,1076.1 ; 2164.04,1163.8 2164.04,1442.6 ; 2164.04,1677.6 2164.04,1741.2 ; 2164.04,1871.2 2164.04,2028.7 ; 2164.04,2183.7 2164.04,2273.3 ; 2164.04,3433.1 2164.04,3631.8 ; 2164.04,4151.1 2164.04,4319.3 ; 2164.04,4454.3 2164.04,4523 ; 2164.04,4757.4 2164.04,4841.9 ; 2169.94,1081.9 2198.44,1081.9 ; 2170.94,1156.9 2197.44,1156.9 ; 2171.64,1106.9 2196.64,1106.9 ; 2171.64,1131.9 2196.64,1131.9 ; 2172.94,4531.9 4450.24,4531.9 ; 2189.04,906.9 2189.04,1442.6 ; 2189.04,1677.6 2189.04,1728.7 ; 2189.04,1883.7 2189.04,2028.7 ; 2189.04,2183.7 2189.04,2273.3 ; 2189.04,3433.1 2189.04,3606.8 ; 2189.04,4151.1 2189.04,4319.3 ; 2189.04,4454.3 2189.04,4548 ; 2189.04,4757.4 2189.04,4841.9 ; 2192.44,3431.9 2222.74,3431.9 ; 2197.94,4556.9 4450.24,4556.9 ; 2210.14,4581.9 4450.24,4581.9 ; 2210.14,4606.9 4450.24,4606.9 ; 2214.04,906.9 2214.04,1066.3 ; 2214.04,1173.6 2214.04,1442.6 ; 2214.04,1677.6 2214.04,1728.7 ; 2214.04,1883.7 2214.04,2028.7 ; 2214.04,2183.7 2214.04,2273.3 ; 2214.04,3410.3 2214.04,3581.8 ; 2214.04,4151.1 2214.04,4319.3 ; 2214.04,4454.3 2214.04,4622.4 ; 2214.04,4757.4 2214.04,4841.9 ; 2217.44,3406.9 2222.74,3406.9 ; 2233.74,3681.9 2253.24,3681.9 ; 2233.74,3706.9 2253.24,3706.9 ; 2233.74,3731.9 2253.24,3731.9 ; 2233.74,3756.9 2253.24,3756.9 ; 2233.74,3781.9 3376.14,3781.9 ; 2233.74,3806.9 4033.74,3806.9 ; 2233.74,3831.9 4033.74,3831.9 ; 2233.74,3856.9 2267.24,3856.9 ; 2233.74,3881.9 2267.24,3881.9 ; 2233.74,3906.9 2267.24,3906.9 ; 2233.74,3931.9 2267.24,3931.9 ; 2233.74,3956.9 2267.24,3956.9 ; 2233.74,3981.9 2267.24,3981.9 ; 2233.74,4006.9 2267.24,4006.9 ; 2237.94,3656.9 2253.24,3656.9 ; 2239.04,906.9 2239.04,1041.3 ; 2239.04,1198.6 2239.04,1442.6 ; 2239.04,1677.6 2239.04,1728.7 ; 2239.04,1883.7 2239.04,2028.7 ; 2239.04,2183.7 2239.04,2273.3 ; 2239.04,3655.8 2239.04,4016.1 ; 2239.04,4151.1 2239.04,4319.3 ; 2239.04,4454.3 2239.04,4622.4 ; 2239.04,4757.4 2239.04,4841.9 ; 2253.24,1456.9 2346.54,1456.9 ; 2253.24,1481.9 2346.54,1481.9 ; 2253.24,1506.9 2346.54,1506.9 ; 2253.24,1531.9 2346.54,1531.9 ; 2253.24,1556.9 2346.54,1556.9 ; 2253.24,1581.9 2346.54,1581.9 ; 2253.24,1606.9 2346.54,1606.9 ; 2253.24,1631.9 2346.54,1631.9 ; 2253.24,1656.9 2346.54,1656.9 ; 2262.94,3631.9 2274.74,3631.9 ; 2264.04,906.9 2264.04,1032.4 ; 2264.04,1207.4 2264.04,1728.7 ; 2264.04,1883.7 2264.04,2028.7 ; 2264.04,2183.7 2264.04,2273.3 ; 2264.04,2696.3 2264.04,2706.3 ; 2264.04,3630.8 2264.04,3642.1 ; 2264.04,3777.1 2264.04,4016.1 ; 2264.04,4151.1 2264.04,4319.3 ; 2264.04,4454.3 2264.04,4622.4 ; 2264.04,4757.4 2264.04,4841.9 ; 2266.24,4031.9 3976.44,4031.9 ; 2266.24,4056.9 3951.44,4056.9 ; 2266.24,4081.9 3926.44,4081.9 ; 2266.24,4106.9 3901.44,4106.9 ; 2266.24,4131.9 3876.44,4131.9 ; 2266.24,4331.9 3676.44,4331.9 ; 2266.24,4431.9 4450.24,4431.9 ; 2278.44,2681.9 2695.14,2681.9 ; 2280.24,1731.9 2366.04,1731.9 ; 2280.24,1881.9 2366.04,1881.9 ; 2289.04,906.9 2289.04,1032.4 ; 2289.04,1207.4 2289.04,1740 ; 2289.04,1870 2289.04,2027.5 ; 2289.04,2182.5 2289.04,2273.3 ; 2289.04,2671.3 2289.04,2706.3 ; 2289.04,3777.1 2289.04,3852.6 ; 2289.04,4007.6 2289.04,4152.6 ; 2289.04,4307.6 2289.04,4351.8 ; 2289.04,4421.8 2289.04,4622.4 ; 2289.04,4757.4 2289.04,4841.9 ; 2303.44,2656.9 2695.14,2656.9 ; 2314.04,906.9 2314.04,1032.4 ; 2314.04,1207.4 2314.04,1740 ; 2314.04,1870 2314.04,2027.5 ; 2314.04,2182.5 2314.04,2273.3 ; 2314.04,2646.3 2314.04,2706.3 ; 2314.04,3777.1 2314.04,3852.6 ; 2314.04,4007.6 2314.04,4152.6 ; 2314.04,4307.6 2314.04,4351.8 ; 2314.04,4421.8 2314.04,4622.4 ; 2314.04,4757.4 2314.04,4841.9 ; 2320.94,1206.9 2447.44,1206.9 ; 2328.44,2631.9 2695.14,2631.9 ; 2339.04,906.9 2339.04,1051.1 ; 2339.04,1188.8 2339.04,1740 ; 2339.04,1870 2339.04,2027.5 ; 2339.04,2182.5 2339.04,2273.3 ; 2339.04,2621.3 2339.04,2706.3 ; 2339.04,3777.1 2339.04,3852.6 ; 2339.04,4007.6 2339.04,4152.6 ; 2339.04,4307.6 2339.04,4351.8 ; 2339.04,4421.8 2339.04,4622.4 ; 2339.04,4757.4 2339.04,4841.9 ; 2344.94,1056.9 2423.44,1056.9 ; 2345.94,1181.9 2422.44,1181.9 ; 2353.44,2606.9 2695.14,2606.9 ; 2364.04,906.9 2364.04,1076.1 ; 2364.04,1163.8 2364.04,1442.6 ; 2364.04,1677.6 2364.04,1740 ; 2364.04,1870 2364.04,2027.5 ; 2364.04,2182.5 2364.04,2273.3 ; 2364.04,2596.3 2364.04,2706.3 ; 2364.04,3777.1 2364.04,3852.6 ; 2364.04,4007.6 2364.04,4152.6 ; 2364.04,4307.6 2364.04,4351.8 ; 2364.04,4421.8 2364.04,4622.4 ; 2364.04,4757.4 2364.04,4841.9 ; 2369.94,1081.9 2398.44,1081.9 ; 2370.94,1156.9 2397.44,1156.9 ; 2371.64,1106.9 2396.64,1106.9 ; 2371.64,1131.9 2396.64,1131.9 ; 2378.34,2581.9 2695.14,2581.9 ; 2389.04,906.9 2389.04,1442.6 ; 2389.04,1677.6 2389.04,1727.5 ; 2389.04,1882.5 2389.04,2027.5 ; 2389.04,2182.5 2389.04,2273.3 ; 2389.04,2571.2 2389.04,2706.3 ; 2389.04,3777.1 2389.04,3852.6 ; 2389.04,4007.6 2389.04,4152.6 ; 2389.04,4307.6 2389.04,4351.8 ; 2389.04,4421.8 2389.04,4622.4 ; 2389.04,4757.4 2389.04,4841.9 ; 2403.34,2556.9 2695.14,2556.9 ; 2414.04,906.9 2414.04,1066.3 ; 2414.04,1173.6 2414.04,1442.6 ; 2414.04,1677.6 2414.04,1727.5 ; 2414.04,1882.5 2414.04,2027.5 ; 2414.04,2182.5 2414.04,2273.3 ; 2414.04,2546.2 2414.04,2706.3 ; 2414.04,3777.1 2414.04,3852.6 ; 2414.04,4007.6 2414.04,4152.6 ; 2414.04,4307.6 2414.04,4351.8 ; 2414.04,4421.8 2414.04,4622.4 ; 2414.04,4757.4 2414.04,4841.9 ; 2421.24,2706.9 2695.14,2706.9 ; 2421.24,2731.9 2695.14,2731.9 ; 2421.24,2756.9 2695.14,2756.9 ; 2421.24,2781.9 2695.14,2781.9 ; 2421.24,2806.9 2695.14,2806.9 ; 2428.34,2531.9 2712.74,2531.9 ; 2439.04,906.9 2439.04,1041.3 ; 2439.04,1198.6 2439.04,1442.6 ; 2439.04,1677.6 2439.04,1727.5 ; 2439.04,1882.5 2439.04,2027.5 ; 2439.04,2182.5 2439.04,2273.3 ; 2439.04,2521.2 2439.04,2813.9 ; 2439.04,3777.1 2439.04,3852.6 ; 2439.04,4007.6 2439.04,4152.6 ; 2439.04,4307.6 2439.04,4351.8 ; 2439.04,4421.8 2439.04,4622.4 ; 2439.04,4757.4 2439.04,4841.9 ; 2441.84,4631.9 3573.14,4631.9 ; 2441.84,4656.9 3548.14,4656.9 ; 2441.84,4681.9 3536.84,4681.9 ; 2441.84,4706.9 3536.84,4706.9 ; 2441.84,4731.9 3536.84,4731.9 ; 2441.84,4756.9 3553.84,4756.9 ; 2453.34,2506.9 2743.44,2506.9 ; 2464.04,906.9 2464.04,1032.4 ; 2464.04,1207.4 2464.04,1442.6 ; 2464.04,1677.6 2464.04,1727.5 ; 2464.04,1882.5 2464.04,2027.5 ; 2464.04,2182.5 2464.04,2273.3 ; 2464.04,2496.2 2464.04,2813.9 ; 2464.04,3777.1 2464.04,3852.6 ; 2464.04,4007.6 2464.04,4152.6 ; 2464.04,4307.6 2464.04,4351.8 ; 2464.04,4421.8 2464.04,4841.9 ; 2478.34,2481.9 2872.24,2481.9 ; 2481.04,1731.9 2565.54,1731.9 ; 2481.04,1881.9 2565.54,1881.9 ; 2481.54,1456.9 2572.04,1456.9 ; 2481.54,1481.9 2572.04,1481.9 ; 2481.54,1506.9 2572.04,1506.9 ; 2481.54,1531.9 2572.04,1531.9 ; 2481.54,1556.9 2572.04,1556.9 ; 2481.54,1581.9 2572.04,1581.9 ; 2481.54,1606.9 2572.04,1606.9 ; 2481.54,1631.9 2572.04,1631.9 ; 2481.54,1656.9 2572.04,1656.9 ; 2486.34,2431.9 2857.84,2431.9 ; 2486.34,2456.9 2857.84,2456.9 ; 2489.04,906.9 2489.04,1032.4 ; 2489.04,1207.4 2489.04,1740 ; 2489.04,1870 2489.04,2027.5 ; 2489.04,2182.5 2489.04,2273.3 ; 2489.04,2408.3 2489.04,2813.9 ; 2489.04,3777.1 2489.04,3852.6 ; 2489.04,4007.6 2489.04,4152.6 ; 2489.04,4307.6 2489.04,4351.8 ; 2489.04,4421.8 2489.04,4841.9 ; 2514.04,906.9 2514.04,1032.4 ; 2514.04,1207.4 2514.04,1740 ; 2514.04,1870 2514.04,2027.5 ; 2514.04,2182.5 2514.04,2273.3 ; 2514.04,2408.3 2514.04,2813.9 ; 2514.04,3777.1 2514.04,3852.6 ; 2514.04,4007.6 2514.04,4152.6 ; 2514.04,4307.6 2514.04,4351.8 ; 2514.04,4421.8 2514.04,4841.9 ; 2518.84,2281.9 2994.34,2281.9 ; 2518.84,2306.9 2994.34,2306.9 ; 2518.84,2331.9 2994.34,2331.9 ; 2518.84,2356.9 2857.84,2356.9 ; 2518.84,2381.9 2857.84,2381.9 ; 2518.84,2406.9 2857.84,2406.9 ; 2520.84,1206.9 2647.24,1206.9 ; 2524.94,2831.9 2695.14,2831.9 ; 2539.04,906.9 2539.04,1051.2 ; 2539.04,1188.7 2539.04,1740 ; 2539.04,1870 2539.04,2027.5 ; 2539.04,2182.5 2539.04,2847.9 ; 2539.04,3777.1 2539.04,3852.6 ; 2539.04,4007.6 2539.04,4152.6 ; 2539.04,4307.6 2539.04,4351.8 ; 2539.04,4421.8 2539.04,4841.9 ; 2544.74,1056.9 2623.34,1056.9 ; 2545.84,1181.9 2622.24,1181.9 ; 2564.04,906.9 2564.04,1076.2 ; 2564.04,1163.7 2564.04,1740 ; 2564.04,1870 2564.04,2027.5 ; 2564.04,2182.5 2564.04,2847.9 ; 2564.04,3777.1 2564.04,3852.6 ; 2564.04,4007.6 2564.04,4152.6 ; 2564.04,4307.6 2564.04,4351.8 ; 2564.04,4421.8 2564.04,4841.9 ; 2569.74,1081.9 2598.34,1081.9 ; 2570.84,1156.9 2597.24,1156.9 ; 2571.54,1106.9 2596.54,1106.9 ; 2571.54,1131.9 2596.54,1131.9 ; 2589.04,906.9 2589.04,1442.2 ; 2589.04,1677.2 2589.04,1727.5 ; 2589.04,1882.5 2589.04,2027.5 ; 2589.04,2182.5 2589.04,2847.9 ; 2589.04,3777.1 2589.04,3852.6 ; 2589.04,4007.6 2589.04,4152.6 ; 2589.04,4307.6 2589.04,4351.8 ; 2589.04,4421.8 2589.04,4841.9 ; 2614.04,906.9 2614.04,1066.2 ; 2614.04,1173.7 2614.04,1442.2 ; 2614.04,1677.2 2614.04,1727.5 ; 2614.04,1882.5 2614.04,2027.5 ; 2614.04,2182.5 2614.04,2847.9 ; 2614.04,3777.1 2614.04,3852.6 ; 2614.04,4007.6 2614.04,4152.6 ; 2614.04,4307.6 2614.04,4351.8 ; 2614.04,4421.8 2614.04,4841.9 ; 2639.04,906.9 2639.04,1041.2 ; 2639.04,1198.7 2639.04,1442.2 ; 2639.04,1677.2 2639.04,1727.5 ; 2639.04,1882.5 2639.04,2027.5 ; 2639.04,2182.5 2639.04,2847.9 ; 2639.04,3777.1 2639.04,3852.6 ; 2639.04,4007.6 2639.04,4152.6 ; 2639.04,4307.6 2639.04,4351.8 ; 2639.04,4421.8 2639.04,4841.9 ; 2664.04,906.9 2664.04,1032.4 ; 2664.04,1207.4 2664.04,1442.2 ; 2664.04,1677.2 2664.04,1727.5 ; 2664.04,1882.5 2664.04,2027.5 ; 2664.04,2182.5 2664.04,2847.9 ; 2664.04,3777.1 2664.04,3852.6 ; 2664.04,4007.6 2664.04,4152.6 ; 2664.04,4307.6 2664.04,4351.8 ; 2664.04,4421.8 2664.04,4841.9 ; 2680.54,1731.9 2766.74,1731.9 ; 2680.54,1881.9 4126.84,1881.9 ; 2680.54,2181.9 2994.34,2181.9 ; 2689.04,906.9 2689.04,1032.4 ; 2689.04,1207.4 2689.04,1442.2 ; 2689.04,1677.2 2689.04,1738.8 ; 2689.04,1868.8 2689.04,2026.3 ; 2689.04,2181.3 2689.04,2847.9 ; 2689.04,3777.1 2689.04,3852.6 ; 2689.04,4007.6 2689.04,4152.6 ; 2689.04,4307.6 2689.04,4351.8 ; 2689.04,4421.8 2689.04,4841.9 ; 2707.04,1456.9 2797.24,1456.9 ; 2707.04,1481.9 2797.24,1481.9 ; 2707.04,1506.9 2797.24,1506.9 ; 2707.04,1531.9 2797.24,1531.9 ; 2707.04,1556.9 2797.24,1556.9 ; 2707.04,1581.9 2797.24,1581.9 ; 2707.04,1606.9 2797.24,1606.9 ; 2707.04,1631.9 2797.24,1631.9 ; 2707.04,1656.9 2797.24,1656.9 ; 2714.04,906.9 2714.04,1032.4 ; 2714.04,1207.4 2714.04,1738.8 ; 2714.04,1868.8 2714.04,2026.3 ; 2714.04,2181.3 2714.04,2530.6 ; 2714.04,3777.1 2714.04,3852.6 ; 2714.04,4007.6 2714.04,4152.6 ; 2714.04,4307.6 2714.04,4351.8 ; 2714.04,4421.8 2714.04,4841.9 ; 2720.84,1206.9 2847.24,1206.9 ; 2739.04,906.9 2739.04,1051.2 ; 2739.04,1188.7 2739.04,1738.8 ; 2739.04,1868.8 2739.04,2026.3 ; 2739.04,2181.3 2739.04,2509.3 ; 2739.04,3777.1 2739.04,3852.6 ; 2739.04,4007.6 2739.04,4152.6 ; 2739.04,4307.6 2739.04,4351.8 ; 2739.04,4421.8 2739.04,4841.9 ; 2744.74,1056.9 2823.34,1056.9 ; 2745.84,1181.9 2822.24,1181.9 ; 2755.64,3631.9 3226.14,3631.9 ; 2764.04,906.9 2764.04,1076.2 ; 2764.04,1163.7 2764.04,1738.8 ; 2764.04,1868.8 2764.04,2026.3 ; 2764.04,2181.3 2764.04,2491.8 ; 2764.04,3622.2 2764.04,3642.1 ; 2764.04,3777.1 2764.04,3852.6 ; 2764.04,4007.6 2764.04,4152.6 ; 2764.04,4307.6 2764.04,4351.8 ; 2764.04,4421.8 2764.04,4841.9 ; 2765.14,2606.9 2994.34,2606.9 ; 2765.14,2631.9 2994.34,2631.9 ; 2765.14,2656.9 2994.34,2656.9 ; 2765.14,2681.9 2994.34,2681.9 ; 2765.14,2706.9 2994.34,2706.9 ; 2765.14,2731.9 2994.34,2731.9 ; 2765.14,2756.9 2994.34,2756.9 ; 2769.74,1081.9 2798.34,1081.9 ; 2770.84,1156.9 2797.24,1156.9 ; 2771.54,1106.9 2796.54,1106.9 ; 2771.54,1131.9 2796.54,1131.9 ; 2788.14,3656.9 3251.14,3656.9 ; 2788.14,3681.9 3276.14,3681.9 ; 2788.14,3706.9 3301.14,3706.9 ; 2788.14,3731.9 3326.14,3731.9 ; 2788.14,3756.9 3351.14,3756.9 ; 2789.04,906.9 2789.04,1726.3 ; 2789.04,1881.3 2789.04,2026.3 ; 2789.04,2181.3 2789.04,2491.8 ; 2789.04,2596.8 2789.04,2779.2 ; 2789.04,3622.2 2789.04,3852.6 ; 2789.04,4007.6 2789.04,4152.6 ; 2789.04,4307.6 2789.04,4351.8 ; 2789.04,4421.8 2789.04,4841.9 ; 2814.04,906.9 2814.04,1066.2 ; 2814.04,1173.7 2814.04,1440.2 ; 2814.04,1675.2 2814.04,1726.3 ; 2814.04,1881.3 2814.04,2026.3 ; 2814.04,2181.3 2814.04,2491.8 ; 2814.04,2596.8 2814.04,2779.2 ; 2814.04,3622.2 2814.04,3852.6 ; 2814.04,4007.6 2814.04,4152.6 ; 2814.04,4307.6 2814.04,4351.8 ; 2814.04,4421.8 2814.04,4841.9 ; 2839.04,906.9 2839.04,1041.2 ; 2839.04,1198.7 2839.04,1440.2 ; 2839.04,1675.2 2839.04,1726.3 ; 2839.04,1881.3 2839.04,2026.3 ; 2839.04,2181.3 2839.04,2491.8 ; 2839.04,2596.8 2839.04,2779.2 ; 2839.04,3622.2 2839.04,3852.6 ; 2839.04,4007.6 2839.04,4152.6 ; 2839.04,4307.6 2839.04,4351.8 ; 2839.04,4421.8 2839.04,4841.9 ; 2858.44,2506.9 2869.24,2506.9 ; 2858.44,2581.9 2994.34,2581.9 ; 2858.44,2781.9 2994.34,2781.9 ; 2858.44,3231.9 3034.84,3231.9 ; 2864.04,906.9 2864.04,1032.4 ; 2864.04,1207.4 2864.04,1440.2 ; 2864.04,1675.2 2864.04,1726.3 ; 2864.04,1881.3 2864.04,2026.3 ; 2864.04,2181.3 2864.04,2345.1 ; 2864.04,2460.1 2864.04,2509.3 ; 2864.04,2579.3 2864.04,2796.7 ; 2864.04,3226.9 2864.04,3239.6 ; 2864.04,3622.2 2864.04,3852.6 ; 2864.04,4007.6 2864.04,4152.6 ; 2864.04,4307.6 2864.04,4351.8 ; 2864.04,4421.8 2864.04,4841.9 ; 2881.74,1731.9 4126.84,1731.9 ; 2881.74,1756.9 4140.94,1756.9 ; 2881.74,1781.9 4165.94,1781.9 ; 2881.74,1806.9 4450.24,1806.9 ; 2881.74,1831.9 4165.24,1831.9 ; 2881.74,1856.9 4140.24,1856.9 ; 2881.74,2031.9 4450.24,2031.9 ; 2881.74,2056.9 3220.44,2056.9 ; 2881.74,2156.9 2984.94,2156.9 ; 2888.64,2806.9 2994.34,2806.9 ; 2889.04,906.9 2889.04,1032.4 ; 2889.04,1207.4 2889.04,1440.2 ; 2889.04,1675.2 2889.04,2068.8 ; 2889.04,2138.8 2889.04,2345.1 ; 2889.04,2579.3 2889.04,2807.3 ; 2889.04,3212.4 2889.04,3239.6 ; 2889.04,3622.2 2889.04,3852.6 ; 2889.04,4007.6 2889.04,4152.6 ; 2889.04,4307.6 2889.04,4351.8 ; 2889.04,4421.8 2889.04,4841.9 ; 2894.54,3206.9 3034.84,3206.9 ; 2913.64,2831.9 2994.34,2831.9 ; 2914.04,906.9 2914.04,1032.4 ; 2914.04,1207.4 2914.04,1440.2 ; 2914.04,1675.2 2914.04,2068.8 ; 2914.04,2138.8 2914.04,2345.1 ; 2914.04,2561.1 2914.04,2832.3 ; 2914.04,3187.4 2914.04,3239.6 ; 2914.04,3622.2 2914.04,3852.6 ; 2914.04,4007.6 2914.04,4152.6 ; 2914.04,4307.6 2914.04,4351.8 ; 2914.04,4421.8 2914.04,4841.9 ; 2918.24,2556.9 2994.34,2556.9 ; 2919.54,3181.9 3034.84,3181.9 ; 2920.64,3106.9 3057.34,3106.9 ; 2920.64,3131.9 3057.34,3131.9 ; 2920.64,3156.9 3034.84,3156.9 ; 2920.84,1206.9 3237.44,1206.9 ; 2922.64,2856.9 2994.04,2856.9 ; 2922.64,2881.9 2976.64,2881.9 ; 2922.64,2906.9 2976.64,2906.9 ; 2932.24,1456.9 3220.44,1456.9 ; 2932.24,1481.9 3195.44,1481.9 ; 2932.24,1506.9 3186.24,1506.9 ; 2932.24,1531.9 3186.24,1531.9 ; 2932.24,1556.9 3196.04,1556.9 ; 2932.24,1581.9 3221.04,1581.9 ; 2932.24,1606.9 4450.24,1606.9 ; 2932.24,1631.9 4165.24,1631.9 ; 2932.24,1656.9 4140.24,1656.9 ; 2933.14,3031.9 2962.14,3031.9 ; 2933.14,3056.9 2962.14,3056.9 ; 2933.14,3081.9 2962.14,3081.9 ; 2935.14,2931.9 2964.14,2931.9 ; 2935.14,2956.9 2964.14,2956.9 ; 2935.14,2981.9 2964.14,2981.9 ; 2935.14,3006.9 2962.14,3006.9 ; 2939.04,906.9 2939.04,1051.2 ; 2939.04,1188.7 2939.04,2068.8 ; 2939.04,2138.8 2939.04,2345.1 ; 2939.04,2536.1 2939.04,3239.6 ; 2939.04,3622.2 2939.04,3852.6 ; 2939.04,4007.6 2939.04,4152.6 ; 2939.04,4307.6 2939.04,4351.8 ; 2939.04,4421.8 2939.04,4841.9 ; 2942.24,2481.9 2994.34,2481.9 ; 2942.24,2506.9 2994.34,2506.9 ; 2942.24,2531.9 2994.34,2531.9 ; 2944.74,1056.9 3227.64,1056.9 ; 2945.84,1181.9 3212.44,1181.9 ; 2952.84,2356.9 2981.84,2356.9 ; 2952.84,2381.9 2981.84,2381.9 ; 2952.84,2406.9 2981.84,2406.9 ; 2952.84,2431.9 2981.84,2431.9 ; 2952.84,2456.9 2981.84,2456.9 ; 2964.04,906.9 2964.04,1076.2 ; 2964.04,1163.7 2964.04,2068.8 ; 2964.04,2138.8 2964.04,2990.7 ; 2964.04,3105.7 2964.04,3239.6 ; 2964.04,3622.2 2964.04,3852.6 ; 2964.04,4007.6 2964.04,4152.6 ; 2964.04,4307.6 2964.04,4351.8 ; 2964.04,4421.8 2964.04,4841.9 ; 2969.74,1081.9 3202.64,1081.9 ; 2970.84,1156.9 3193.84,1156.9 ; 2971.54,1106.9 3193.84,1106.9 ; 2971.54,1131.9 3193.84,1131.9 ; 2989.04,906.9 2989.04,2068.8 ; 2989.04,2161 2989.04,2345.1 ; 2989.04,2460.1 2989.04,2861.9 ; 2989.04,3105.7 2989.04,3239.6 ; 2989.04,3622.2 2989.04,3852.6 ; 2989.04,4007.6 2989.04,4152.6 ; 2989.04,4307.6 2989.04,4351.8 ; 2989.04,4421.8 2989.04,4841.9 ; 3008.94,2081.9 3195.44,2081.9 ; 3014.04,906.9 3014.04,2087 ; 3014.04,3105.7 3014.04,3239.6 ; 3014.04,3622.2 3014.04,3852.6 ; 3014.04,4007.6 3014.04,4152.6 ; 3014.04,4307.6 3014.04,4351.8 ; 3014.04,4421.8 3014.04,4841.9 ; 3033.94,2106.9 3186.24,2106.9 ; 3039.04,906.9 3039.04,2112 ; 3039.04,3105.7 3039.04,3137.4 ; 3039.04,3622.2 3039.04,3852.6 ; 3039.04,4007.6 3039.04,4152.6 ; 3039.04,4307.6 3039.04,4351.8 ; 3039.04,4421.8 3039.04,4841.9 ; 3057.14,3031.9 3057.34,3031.9 ; 3057.14,3056.9 3057.34,3056.9 ; 3057.14,3081.9 3057.34,3081.9 ; 3058.94,2131.9 3186.24,2131.9 ; 3064.04,906.9 3064.04,2137 ; 3064.04,3622.2 3064.04,3852.6 ; 3064.04,4007.6 3064.04,4152.6 ; 3064.04,4307.6 3064.04,4351.8 ; 3064.04,4421.8 3064.04,4841.9 ; 3064.34,2156.9 3196.04,2156.9 ; 3064.34,2181.9 3221.04,2181.9 ; 3064.34,2206.9 3389.94,2206.9 ; 3064.34,2231.9 3198.34,2231.9 ; 3064.34,2256.9 3198.34,2256.9 ; 3064.34,2281.9 3187.14,2281.9 ; 3064.34,2306.9 3169.94,2306.9 ; 3064.34,2331.9 3137.44,2331.9 ; 3076.84,2356.9 3137.44,2356.9 ; 3076.84,2381.9 3137.44,2381.9 ; 3082.14,4156.9 3851.44,4156.9 ; 3082.14,4306.9 3701.44,4306.9 ; 3083.04,2406.9 3137.44,2406.9 ; 3089.04,906.9 3089.04,2412.9 ; 3089.04,3622.2 3089.04,3852.6 ; 3089.04,4007.6 3089.04,4165.1 ; 3089.04,4295.1 3089.04,4351.8 ; 3089.04,4421.8 3089.04,4841.9 ; 3114.04,906.9 3114.04,2414.9 ; 3114.04,3622.2 3114.04,3852.6 ; 3114.04,4007.6 3114.04,4165.1 ; 3114.04,4295.1 3114.04,4351.8 ; 3114.04,4421.8 3114.04,4841.9 ; 3139.04,906.9 3139.04,2311.5 ; 3139.04,3622.2 3139.04,3852.6 ; 3139.04,4007.6 3139.04,4165.1 ; 3139.04,4295.1 3139.04,4351.8 ; 3139.04,4421.8 3139.04,4841.9 ; 3164.04,906.9 3164.04,2311.5 ; 3164.04,3622.2 3164.04,3852.6 ; 3164.04,4007.6 3164.04,4165.1 ; 3164.04,4295.1 3164.04,4351.8 ; 3164.04,4421.8 3164.04,4841.9 ; 3176.44,2456.9 4450.24,2456.9 ; 3182.14,3856.9 4033.74,3856.9 ; 3182.14,3881.9 4033.74,3881.9 ; 3182.14,3906.9 4033.74,3906.9 ; 3182.14,3931.9 4033.74,3931.9 ; 3182.14,3956.9 4033.74,3956.9 ; 3182.14,3981.9 4026.44,3981.9 ; 3182.14,4006.9 4001.44,4006.9 ; 3189.04,906.9 3189.04,1488.4 ; 3189.04,1549.9 3189.04,2088.4 ; 3189.04,2149.9 3189.04,2280 ; 3189.04,2446.5 3189.04,2469.5 ; 3189.04,3622.2 3189.04,4165.1 ; 3189.04,4295.1 3189.04,4351.8 ; 3189.04,4421.8 3189.04,4841.9 ; 3189.64,4181.9 3826.44,4181.9 ; 3189.64,4206.9 3801.44,4206.9 ; 3189.64,4231.9 3776.44,4231.9 ; 3189.64,4256.9 3751.44,4256.9 ; 3189.64,4281.9 3726.44,4281.9 ; 3194.24,2481.9 4450.24,2481.9 ; 3194.24,2506.9 4450.24,2506.9 ; 3194.24,2531.9 3208.84,2531.9 ; 3194.24,2556.9 3208.84,2556.9 ; 3194.24,2581.9 3208.84,2581.9 ; 3194.24,2606.9 3208.84,2606.9 ; 3194.24,2631.9 3208.84,2631.9 ; 3194.24,2656.9 3208.84,2656.9 ; 3194.24,2681.9 4450.24,2681.9 ; 3194.24,2706.9 4450.24,2706.9 ; 3194.24,2731.9 4450.24,2731.9 ; 3194.24,2756.9 4450.24,2756.9 ; 3194.24,2781.9 3764.34,2781.9 ; 3194.24,2806.9 3739.34,2806.9 ; 3194.24,2831.9 3208.84,2831.9 ; 3194.24,2856.9 3208.84,2856.9 ; 3194.24,2881.9 3208.84,2881.9 ; 3194.24,2906.9 3208.84,2906.9 ; 3194.24,2931.9 3208.84,2931.9 ; 3194.24,2956.9 3208.84,2956.9 ; 3194.24,2981.9 3331.34,2981.9 ; 3194.24,3006.9 3346.44,3006.9 ; 3194.24,3031.9 3298.84,3031.9 ; 3194.24,3056.9 3298.84,3056.9 ; 3194.24,3081.9 3279.14,3081.9 ; 3194.24,3106.9 3257.34,3106.9 ; 3201.84,3131.9 3257.34,3131.9 ; 3214.04,906.9 3214.04,1070.6 ; 3214.04,1183.5 3214.04,1463.4 ; 3214.04,1574.9 3214.04,2063.4 ; 3214.04,2174.9 3214.04,2215.2 ; 3214.04,2446.5 3214.04,2522 ; 3214.04,2677 3214.04,2822 ; 3214.04,2976.9 3214.04,3144 ; 3214.04,3622.2 3214.04,4351.8 ; 3214.04,4421.8 3214.04,4841.9 ; 3226.84,3156.9 3257.34,3156.9 ; 3239.04,906.9 3239.04,1045.6 ; 3239.04,1208.5 3239.04,1451.6 ; 3239.04,1586.6 3239.04,2051.6 ; 3239.04,2186.6 3239.04,2215.2 ; 3239.04,2446.5 3239.04,2522 ; 3239.04,2677 3239.04,2822 ; 3239.04,2976.9 3239.04,3169 ; 3239.04,3644.8 3239.04,4351.8 ; 3239.04,4421.8 3239.04,4841.9 ; 3251.84,3181.9 3257.34,3181.9 ; 3264.04,906.9 3264.04,1039.5 ; 3264.04,1214.5 3264.04,1451.6 ; 3264.04,1586.6 3264.04,2051.6 ; 3264.04,2186.6 3264.04,2215.2 ; 3264.04,2446.5 3264.04,2522 ; 3264.04,2677 3264.04,2822 ; 3264.04,2976.9 3264.04,3097 ; 3264.04,3669.8 3264.04,4351.8 ; 3264.04,4421.8 3264.04,4841.9 ; 3286.44,1581.9 4450.24,1581.9 ; 3286.44,2181.9 3395.54,2181.9 ; 3286.94,1456.9 3391.14,1456.9 ; 3286.94,2056.9 3771.74,2056.9 ; 3289.04,906.9 3289.04,1039.5 ; 3289.04,1214.5 3289.04,1459 ; 3289.04,1579.3 3289.04,2059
